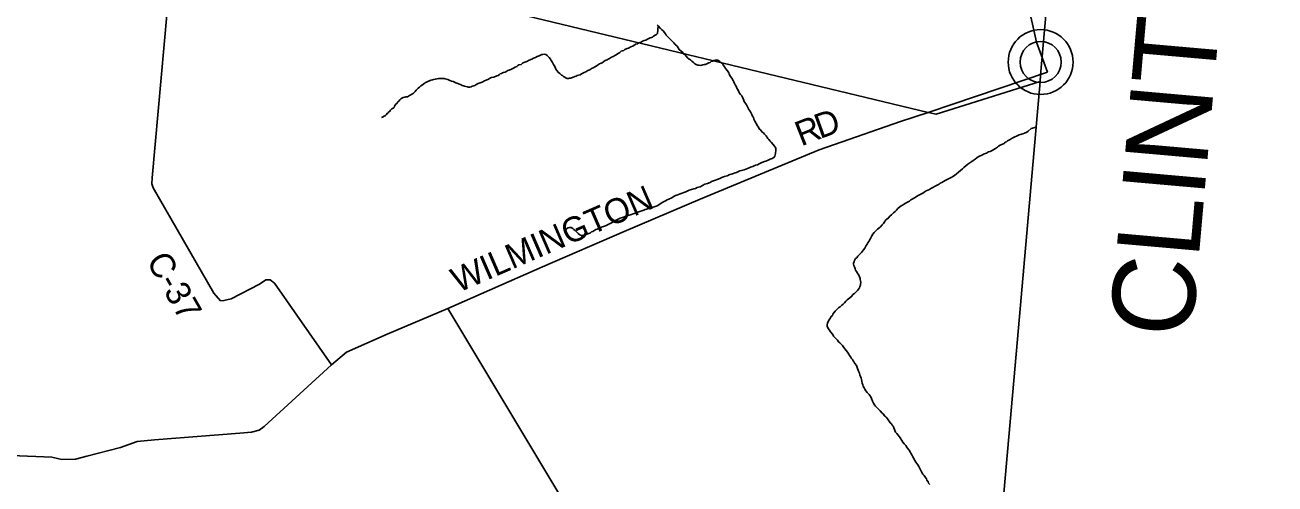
# Model space of a CAD drawing. Extents: x 1310247 to 1664935, y 284496 to 704931.
# Drawn here: x 1535762 to 1550897, y 524552 to 530108 of the extents above; entities that cross this region are included whole.
import ezdxf

# ---------------------------------------------------------------- set-up
doc = ezdxf.new("R2010")
doc.units = 0
for name, color, linetype in [('GM_X_Adjacent_County', 7, 'Continuous'), ('GM_X_Adjacent_County_Text', 7, 'Continuous'), ('GM_X_County_Road_Text', 7, 'Continuous'), ('GM_X_Major_River_Text', 7, 'Continuous'), ('GM_X_Minor_Lake', 7, 'Continuous'), ('GM_X_Minor_River_Text', 7, 'Continuous'), ('GM_X_Township', 7, 'Continuous'), ('GM_X_Township_Road', 7, 'Continuous'), ('GM_X_Unincorporated', 7, 'Continuous')]:
    doc.layers.add(name, color=color, linetype=linetype)

msp = doc.modelspace()

# ---------------------------------------------------------------- linework, layer by layer
at = {"layer": 'GM_X_Adjacent_County'}
for points in [[(1549068, 540794), (1548703, 536779), (1548609, 535719), (1548059, 529500), (1548052, 529426), (1546793, 529028), (1546699, 529050), (1537825, 531187), (1537570, 531248), (1530286, 533001), (1523205, 534705), (1523139, 535585), (1522991, 537923), (1525088, 540691)], [(1520400, 535135), (1523205, 534705), (1530286, 533001), (1537570, 531248), (1537825, 531187), (1546699, 529050), (1546793, 529028), (1548052, 529426), (1547777, 526306), (1547463, 522758), (1547324, 521188), (1546926, 516687), (1546686, 513989), (1546298, 509606)]]:
    msp.add_lwpolyline(points, dxfattribs=at)
at = {"layer": 'GM_X_Adjacent_County_Text'}
msp.add_lwpolyline([(1543136, 476031), (1543818, 482923), (1543861, 483362), (1544123, 486002), (1544212, 487256), (1544429, 489554), (1545002, 495623), (1545013, 495738), (1545078, 496425), (1545353, 499331), (1545798, 504044), (1545822, 504298), (1546298, 509606), (1546686, 513989), (1546926, 516687), (1547324, 521188), (1547463, 522758), (1547777, 526306), (1548052, 529426), (1548059, 529500), (1548609, 535719), (1548703, 536779), (1549068, 540794)], dxfattribs=at)
at = {"layer": 'GM_X_County_Road_Text'}
for points in [[(1539474, 525996), (1538782, 526983), (1538731, 527022), (1538677, 527023), (1538602, 526973), (1538258, 526795), (1538171, 526772), (1538129, 526769), (1538047, 526861), (1537312, 528139), (1537299, 528186), (1537300, 528258), (1537557, 531086), (1537561, 531139), (1537561, 531139)], [(1548141, 529538), (1548010, 529901), (1547901, 530388)], [(1535597, 524898), (1536086, 524876), (1536207, 524849), (1536372, 524852), (1536511, 524888), (1536919, 524995), (1537121, 525066), (1537330, 525087), (1538361, 525169), (1538506, 525179), (1538598, 525202), (1538659, 525246), (1539474, 525996), (1539656, 526147), (1540145, 526365), (1540882, 526678), (1542027, 527182), (1543018, 527607), (1543936, 528001), (1545379, 528598), (1546363, 528942), (1546699, 529050), (1548141, 529538)], [(1545119, 519667), (1544881, 520040), (1544606, 520470), (1540882, 526678)]]:
    msp.add_lwpolyline(points, dxfattribs=at)
at = {"layer": 'GM_X_Major_River_Text'}
msp.add_line((1548059, 529660), (1548059, 529660), dxfattribs=at)
at = {"layer": 'GM_X_Minor_River_Text'}
for points in [[(1543429, 530097), (1543419, 530007), (1543406, 529995), (1543392, 529985), (1543372, 529973), (1543359, 529962), (1543347, 529958), (1543333, 529952), (1543317, 529944), (1543300, 529937), (1543278, 529925), (1543258, 529919), (1543239, 529912), (1543223, 529902), (1543205, 529896), (1543191, 529888), (1543176, 529881), (1543154, 529875), (1543129, 529857), (1543117, 529852), (1543099, 529844), (1543068, 529828), (1543052, 529825), (1543026, 529811), (1543011, 529801), (1542995, 529797), (1542981, 529790), (1542965, 529774), (1542942, 529764), (1542912, 529743), (1542885, 529727), (1542865, 529720), (1542838, 529704), (1542822, 529694), (1542810, 529688), (1542787, 529677), (1542771, 529667), (1542752, 529651), (1542738, 529645), (1542718, 529638), (1542704, 529630), (1542691, 529618), (1542669, 529607), (1542640, 529589), (1542620, 529583), (1542600, 529566), (1542575, 529556), (1542553, 529540), (1542532, 529533), (1542516, 529525), (1542500, 529519), (1542484, 529507), (1542465, 529502), (1542449, 529496), (1542435, 529488), (1542421, 529485), (1542390, 529473), (1542378, 529469), (1542366, 529465), (1542354, 529464), (1542342, 529462), (1542325, 529462), (1542314, 529466), (1542298, 529477), (1542282, 529485), (1542270, 529495), (1542258, 529502), (1542236, 529522), (1542220, 529532), (1542203, 529557), (1542189, 529573), (1542187, 529585), (1542176, 529606), (1542168, 529620), (1542162, 529632), (1542149, 529656), (1542133, 529677), (1542123, 529693), (1542110, 529713), (1542096, 529728), (1542084, 529740), (1542066, 529750), (1542050, 529755), (1542030, 529753), (1542018, 529751), (1542002, 529745), (1541989, 529736), (1541977, 529732), (1541963, 529728), (1541943, 529714), (1541918, 529707), (1541898, 529693), (1541865, 529684), (1541839, 529668), (1541815, 529660), (1541800, 529655), (1541786, 529647), (1541768, 529631), (1541743, 529626), (1541729, 529618), (1541715, 529606)], [(1543415, 530111), (1543429, 530097)], [(1543429, 530097), (1543456, 530064), (1543474, 530050), (1543488, 530038), (1543515, 530001), (1543525, 529987), (1543539, 529974), (1543560, 529950), (1543578, 529934), (1543598, 529913), (1543619, 529891), (1543633, 529874), (1543657, 529852), (1543672, 529831), (1543684, 529811), (1543726, 529776), (1543735, 529760), (1543749, 529750), (1543773, 529727), (1543784, 529711), (1543804, 529694), (1543818, 529688), (1543836, 529670), (1543854, 529655), (1543868, 529643), (1543881, 529633), (1543895, 529626), (1543909, 529624), (1543925, 529622), (1543941, 529619), (1543956, 529621), (1543970, 529625), (1543986, 529629), (1544002, 529632), (1544018, 529638), (1544043, 529650), (1544057, 529655), (1544071, 529665), (1544088, 529671), (1544104, 529679), (1544120, 529682), (1544134, 529682), (1544152, 529682), (1544174, 529667), (1544186, 529653), (1544206, 529641), (1544221, 529620), (1544237, 529598), (1544245, 529580), (1544266, 529553), (1544282, 529531), (1544289, 529513), (1544303, 529486), (1544320, 529464), (1544336, 529437), (1544344, 529419), (1544353, 529399), (1544361, 529383), (1544371, 529368), (1544382, 529342), (1544398, 529318), (1544405, 529299), (1544413, 529285), (1544425, 529267), (1544440, 529249), (1544448, 529234), (1544462, 529208), (1544471, 529184), (1544499, 529143), (1544506, 529125), (1544525, 529084), (1544537, 529070), (1544547, 529056), (1544553, 529042), (1544562, 529023), (1544570, 529005), (1544582, 528987), (1544587, 528967), (1544597, 528946), (1544605, 528932), (1544614, 528914), (1544632, 528889), (1544643, 528871), (1544653, 528851), (1544667, 528841), (1544688, 528812), (1544702, 528802), (1544714, 528785), (1544734, 528767), (1544755, 528736), (1544769, 528722), (1544785, 528704), (1544798, 528691), (1544822, 528661), (1544838, 528640), (1544847, 528626), (1544853, 528612), (1544853, 528598), (1544852, 528582), (1544850, 528566), (1544850, 528552)], [(1541715, 529606), (1541696, 529598), (1541678, 529584), (1541652, 529575), (1541623, 529561), (1541609, 529556), (1541597, 529550), (1541574, 529538), (1541556, 529534), (1541544, 529529), (1541530, 529523), (1541517, 529517), (1541505, 529511), (1541489, 529498), (1541473, 529494), (1541440, 529478), (1541412, 529471), (1541400, 529467), (1541387, 529461), (1541375, 529451), (1541347, 529442), (1541324, 529432), (1541296, 529415), (1541271, 529409), (1541249, 529399), (1541233, 529392), (1541208, 529376), (1541196, 529372), (1541178, 529369), (1541164, 529361), (1541146, 529357), (1541131, 529355), (1541119, 529358), (1541101, 529362), (1541085, 529368), (1541073, 529371), (1541057, 529375), (1541041, 529383), (1541023, 529392), (1540992, 529404), (1540978, 529410), (1540944, 529425), (1540924, 529430), (1540904, 529438), (1540880, 529448), (1540864, 529453), (1540850, 529457), (1540836, 529461), (1540814, 529462), (1540794, 529462), (1540781, 529462), (1540769, 529460), (1540751, 529457), (1540731, 529453), (1540707, 529448), (1540695, 529444), (1540676, 529440), (1540660, 529434), (1540646, 529429), (1540625, 529417), (1540611, 529411), (1540591, 529397), (1540576, 529386), (1540556, 529372), (1540538, 529354), (1540523, 529344), (1540509, 529331), (1540498, 529319), (1540486, 529305), (1540472, 529293), (1540463, 529279), (1540447, 529273), (1540433, 529264), (1540417, 529254), (1540404, 529248), (1540392, 529240), (1540374, 529237), (1540360, 529235), (1540342, 529231), (1540323, 529221), (1540311, 529214), (1540299, 529202), (1540288, 529188), (1540276, 529178), (1540266, 529162), (1540253, 529148), (1540243, 529137), (1540234, 529125), (1540232, 529111), (1540218, 529101), (1540202, 529093), (1540187, 529079), (1540181, 529065), (1540169, 529058), (1540160, 529046), (1540148, 529038), (1540140, 529026), (1540125, 529012), (1540109, 529006), (1540091, 528993), (1540078, 528987)], [(1548006, 528870), (1547946, 528854), (1547907, 528823), (1547893, 528813), (1547863, 528799), (1547844, 528791), (1547828, 528786), (1547800, 528778), (1547784, 528772), (1547768, 528764), (1547748, 528755), (1547732, 528747), (1547715, 528739), (1547689, 528723), (1547675, 528714), (1547659, 528706), (1547645, 528696), (1547629, 528688), (1547616, 528674), (1547596, 528666), (1547570, 528653), (1547550, 528643), (1547536, 528631), (1547513, 528613), (1547493, 528602), (1547473, 528588), (1547449, 528578), (1547428, 528571), (1547404, 528557), (1547376, 528547), (1547362, 528539), (1547348, 528534), (1547317, 528520), (1547303, 528512), (1547285, 528500), (1547265, 528485), (1547243, 528469), (1547226, 528457), (1547200, 528439), (1547178, 528422), (1547153, 528404), (1547129, 528384), (1547111, 528366), (1547088, 528347), (1547064, 528325), (1547038, 528303), (1547022, 528291), (1547003, 528280), (1546975, 528262), (1546961, 528256), (1546943, 528246), (1546920, 528235), (1546902, 528225), (1546884, 528215), (1546862, 528203), (1546844, 528192), (1546830, 528180), (1546805, 528170), (1546781, 528156), (1546755, 528143), (1546731, 528129), (1546714, 528115), (1546674, 528100), (1546648, 528084), (1546632, 528072), (1546607, 528059), (1546569, 528039), (1546541, 528021), (1546524, 528012), (1546502, 528000), (1546486, 527990), (1546470, 527976), (1546456, 527966), (1546437, 527959), (1546409, 527943), (1546385, 527927), (1546371, 527918), (1546355, 527908), (1546330, 527886), (1546314, 527868), (1546296, 527850), (1546277, 527835), (1546253, 527811), (1546239, 527799), (1546214, 527769), (1546196, 527756), (1546182, 527744), (1546174, 527728), (1546155, 527706), (1546139, 527688), (1546119, 527664), (1546098, 527649), (1546084, 527637), (1546070, 527625), (1546060, 527611), (1546045, 527595), (1546029, 527575), (1546017, 527558), (1546009, 527540), (1545998, 527524), (1545988, 527504)], [(1544850, 528552), (1544845, 528536), (1544839, 528522), (1544829, 528504), (1544810, 528494), (1544784, 528483), (1544770, 528477), (1544751, 528467), (1544731, 528460), (1544717, 528454), (1544684, 528444), (1544650, 528429), (1544629, 528415), (1544605, 528410), (1544591, 528404), (1544574, 528394), (1544548, 528387), (1544528, 528379), (1544508, 528373), (1544471, 528356), (1544439, 528348), (1544416, 528343), (1544376, 528323), (1544359, 528318), (1544327, 528308), (1544313, 528302), (1544295, 528299), (1544264, 528283), (1544232, 528274), (1544209, 528266), (1544173, 528249), (1544142, 528239), (1544122, 528230), (1544075, 528214), (1544057, 528203), (1544024, 528189), (1543994, 528180), (1543965, 528166), (1543937, 528151), (1543917, 528147), (1543900, 528141), (1543882, 528129), (1543858, 528126), (1543833, 528116), (1543803, 528107), (1543787, 528099), (1543762, 528087), (1543738, 528082), (1543720, 528072), (1543693, 528065), (1543675, 528057), (1543655, 528049), (1543639, 528044), (1543622, 528038), (1543592, 528018), (1543559, 528001), (1543539, 527991), (1543516, 527979), (1543484, 527962), (1543451, 527942), (1543437, 527931), (1543414, 527921), (1543378, 527906), (1543354, 527900), (1543337, 527894), (1543315, 527887), (1543272, 527873), (1543256, 527866), (1543220, 527854), (1543183, 527843), (1543161, 527833), (1543126, 527824), (1543106, 527814), (1543049, 527797), (1543009, 527784), (1542995, 527778), (1542968, 527768), (1542950, 527761), (1542919, 527745), (1542879, 527722), (1542840, 527702), (1542824, 527695), (1542807, 527687), (1542789, 527679), (1542767, 527670), (1542750, 527664), (1542736, 527658), (1542716, 527650), (1542689, 527637), (1542675, 527631), (1542661, 527625), (1542637, 527610), (1542622, 527604), (1542608, 527594), (1542590, 527586), (1542575, 527579), (1542553, 527571), (1542535, 527565), (1542517, 527560), (1542499, 527562), (1542481, 527570)], [(1542481, 527570), (1542461, 527585), (1542443, 527601), (1542423, 527622), (1542408, 527634), (1542394, 527646), (1542374, 527657), (1542356, 527657), (1542337, 527651), (1542323, 527644), (1542309, 527630)], [(1545988, 527504), (1545978, 527488), (1545966, 527470), (1545959, 527456), (1545947, 527438), (1545939, 527422), (1545929, 527406), (1545914, 527386), (1545904, 527371), (1545892, 527355), (1545878, 527343), (1545863, 527325), (1545847, 527309), (1545833, 527289), (1545819, 527280), (1545806, 527258), (1545800, 527242), (1545794, 527228), (1545794, 527212), (1545799, 527196), (1545805, 527179), (1545813, 527157), (1545819, 527141), (1545828, 527123), (1545840, 527105), (1545850, 527091), (1545862, 527072), (1545866, 527058), (1545873, 527040), (1545875, 527026), (1545879, 527010), (1545881, 526990), (1545878, 526972), (1545876, 526958), (1545868, 526942), (1545864, 526928), (1545854, 526912), (1545841, 526896), (1545827, 526878), (1545807, 526858), (1545786, 526845), (1545772, 526827), (1545750, 526805), (1545734, 526795), (1545717, 526780), (1545699, 526764), (1545685, 526746), (1545669, 526730), (1545650, 526716), (1545630, 526698), (1545614, 526687), (1545595, 526667), (1545571, 526645), (1545557, 526623), (1545543, 526607), (1545538, 526593), (1545524, 526580), (1545516, 526562), (1545499, 526540), (1545485, 526520), (1545477, 526500), (1545475, 526480), (1545476, 526462), (1545486, 526436), (1545504, 526415), (1545514, 526395), (1545541, 526361), (1545553, 526343), (1545569, 526326), (1545583, 526310), (1545600, 526294), (1545610, 526274), (1545626, 526259), (1545640, 526247), (1545660, 526227), (1545677, 526204), (1545689, 526190), (1545705, 526170), (1545719, 526148), (1545736, 526123), (1545746, 526109), (1545760, 526089), (1545770, 526073), (1545782, 526059), (1545791, 526042), (1545801, 526028), (1545811, 526012), (1545829, 525986), (1545838, 525964), (1545852, 525919), (1545865, 525893), (1545871, 525871), (1545879, 525855), (1545885, 525834), (1545890, 525818), (1545894, 525798), (1545898, 525772), (1545906, 525752), (1545911, 525736), (1545921, 525718), (1545931, 525701)], [(1545931, 525701), (1545943, 525681), (1545960, 525661), (1545982, 525637), (1545992, 525622), (1546002, 525606), (1546012, 525588), (1546025, 525554), (1546035, 525532), (1546047, 525511), (1546058, 525493), (1546078, 525475), (1546098, 525452), (1546118, 525436), (1546141, 525410), (1546155, 525397), (1546169, 525379), (1546183, 525367), (1546197, 525353), (1546212, 525328), (1546224, 525312), (1546238, 525292), (1546252, 525282), (1546262, 525266), (1546272, 525251), (1546281, 525233), (1546303, 525179), (1546316, 525163), (1546334, 525142), (1546358, 525110), (1546379, 525077), (1546391, 525059), (1546407, 525039), (1546425, 525019), (1546444, 524990), (1546468, 524960), (1546484, 524934), (1546491, 524919), (1546499, 524903), (1546513, 524879), (1546527, 524853), (1546536, 524837), (1546548, 524816), (1546572, 524784), (1546583, 524764), (1546595, 524740), (1546605, 524723), (1546615, 524699), (1546632, 524671), (1546648, 524653), (1546666, 524630), (1546676, 524614), (1546683, 524600), (1546697, 524580), (1546703, 524564), (1546719, 524545)]]:
    msp.add_lwpolyline(points, dxfattribs=at)
at = {"layer": 'GM_X_Township'}
msp.add_lwpolyline([(1549068, 540794), (1548703, 536779), (1548609, 535719), (1548059, 529500), (1548052, 529426), (1547777, 526306), (1547463, 522758), (1547324, 521188), (1546926, 516687), (1546686, 513989), (1546298, 509606), (1545822, 504298), (1545798, 504044), (1545353, 499331), (1545078, 496425), (1545013, 495738), (1545002, 495623), (1544429, 489554), (1544212, 487256), (1544123, 486002), (1543861, 483362), (1543818, 482923), (1543136, 476031)], dxfattribs=at)
at = {"layer": 'GM_X_Unincorporated'}
for radius in [393, 249]:
    msp.add_circle((1548059, 529660), radius, dxfattribs=at)

# ---------------------------------------------------------------- texts
at = {"layer": 'GM_X_Minor_Lake'}
msp.add_text('CLINTON COUNTY', height=1000, rotation=84.9623, dxfattribs=at).set_placement((1549887, 526304))
at = {"layer": 'GM_X_Township_Road'}
for s, rotation, p in [('R', 21.4825, (1545160, 528637)), ('D', 19.8543, (1545387, 528727)), ('WILMINGTON', 23.4575, (1541006, 526864)), ('C-37', 299.7874, (1537225, 527253))]:
    msp.add_text(s, height=300, rotation=rotation, dxfattribs=at).set_placement(p)

doc.saveas('drawing.dxf')
